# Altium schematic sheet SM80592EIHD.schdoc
size 127 x 101 mm
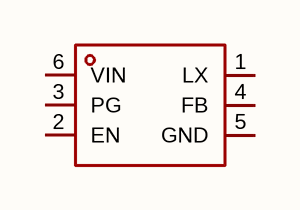
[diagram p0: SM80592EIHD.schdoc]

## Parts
U?  sm80592eihd  [DFN-6_L1.3-W0.9-P0.45-BL]  (value not drawn)

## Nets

Not connected (* = marked no-connect by the designer): U? 1(LX) 2(EN) 3(PG) 4(FB) 5(GND) 6(VIN)

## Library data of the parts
U? = sm80592eihd: 功能类型:降压型;工作电压:2.5V~5.5V;输出电压:-;输出电流:2A;输出类型:可调;; Manufacturer: Silergy(矽力杰); AddInBom: yes; ModelId: ce062897730d434c9673ae002a89ce25; ModelTransform: 51.181,35.827,0,0,0,0,0.003,0.003,0; Function: 降压型; Output Current: 2A; Frequency - Switching: 1.5MHz; Synchronous Rectifier: 是; Number of Outputs: 1; Topology: 降压式; Switch tube (built-in/external): 内置; Output Type: 可调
